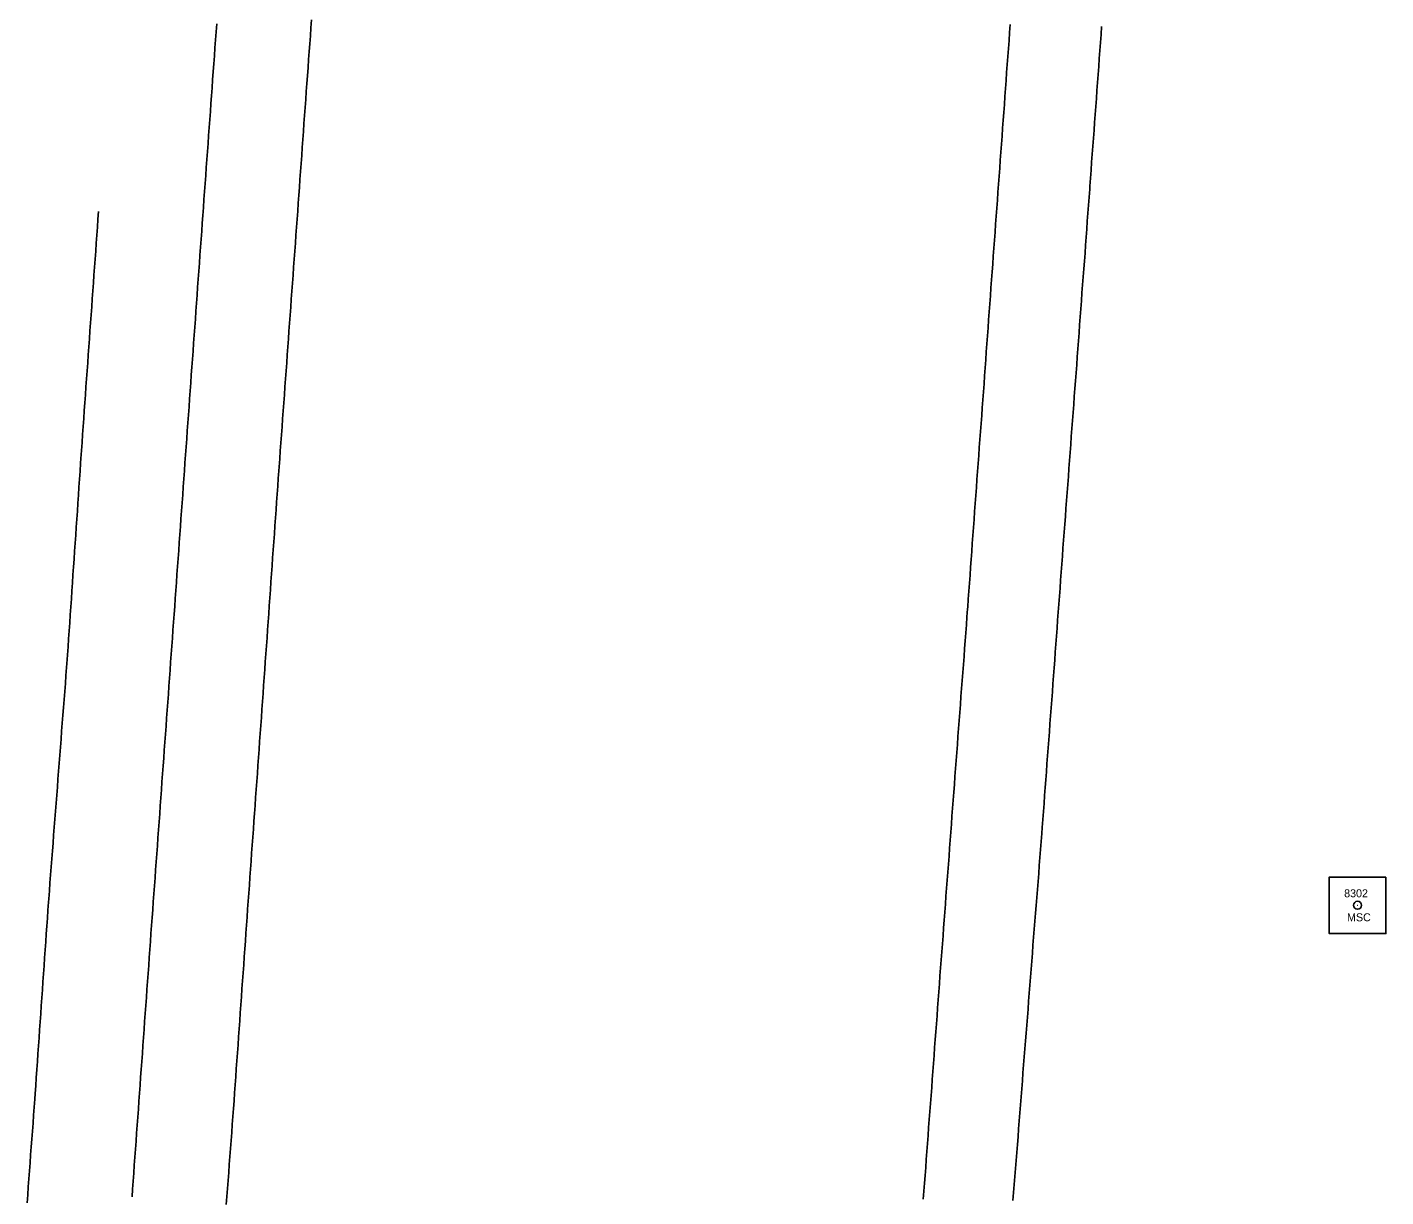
# Model space of a CAD drawing. Extents: x 205929 to 2357175, y -1785700 to 846739.
# Drawn here: x 2023342.3 to 2023512, y 808641.8 to 808787.9 of the extents above; entities that cross this region are included whole.
import ezdxf

# ---------------------------------------------------------------- set-up
doc = ezdxf.new("R2010")
doc.units = 0
for name, color, linetype in [('RD_HC_Survey', 7, 'Continuous'), ('RD_HC_txCode', 7, 'Continuous'), ('RD_Sketch1', 7, 'Continuous'), ('RD_SMD_Locator', 7, 'Continuous')]:
    doc.layers.add(name, color=color, linetype=linetype)

msp = doc.modelspace()

# ---------------------------------------------------------------- linework, layer by layer
at = {"layer": 'RD_HC_Survey'}
msp.add_lwpolyline([(2023512.02, 808681.73), (2023504.95, 808681.73), (2023504.95, 808674.66), (2023512.02, 808674.66)], close=True, dxfattribs=at)
msp.add_circle((2023508.48, 808678.2), 0.5, dxfattribs=at)
at = {"layer": 'RD_Sketch1'}
for points in [[(2023365.93, 808788.35), (2023365.85, 808787.35), (2023365.78, 808786.36), (2023365.71, 808785.36), (2023365.64, 808784.36), (2023365.57, 808783.36), (2023365.49, 808782.37), (2023365.42, 808781.37), (2023365.35, 808780.37), (2023365.28, 808779.37), (2023365.21, 808778.38), (2023365.14, 808777.38), (2023365.06, 808776.38), (2023364.99, 808775.39), (2023364.92, 808774.39), (2023364.85, 808773.39), (2023364.78, 808772.39), (2023364.7, 808771.4), (2023364.63, 808770.4), (2023364.56, 808769.4), (2023364.49, 808768.4), (2023364.42, 808767.41), (2023364.34, 808766.41), (2023364.27, 808765.41), (2023364.2, 808764.41), (2023364.13, 808763.42), (2023364.06, 808762.42), (2023363.98, 808761.42), (2023363.91, 808760.42), (2023363.84, 808759.43), (2023363.77, 808758.43), (2023363.7, 808757.43), (2023363.63, 808756.44), (2023363.55, 808755.44), (2023363.48, 808754.44), (2023363.41, 808753.44), (2023363.34, 808752.45), (2023363.27, 808751.45), (2023363.19, 808750.45), (2023363.12, 808749.45), (2023363.05, 808748.46), (2023362.98, 808747.46), (2023362.91, 808746.46), (2023362.91, 808746.46), (2023362.83, 808745.46), (2023362.76, 808744.47), (2023362.69, 808743.47), (2023362.62, 808742.47), (2023362.55, 808741.47), (2023362.48, 808740.48), (2023362.4, 808739.48), (2023362.33, 808738.48), (2023362.26, 808737.48), (2023362.19, 808736.49), (2023362.12, 808735.49), (2023362.04, 808734.49), (2023361.97, 808733.5), (2023361.9, 808732.5), (2023361.83, 808731.5), (2023361.76, 808730.5), (2023361.68, 808729.51), (2023361.61, 808728.51), (2023361.54, 808727.51), (2023361.47, 808726.51), (2023361.4, 808725.53), (2023361.33, 808724.53), (2023361.25, 808723.53), (2023361.18, 808722.54), (2023361.11, 808721.54), (2023361.04, 808720.54), (2023360.97, 808719.54), (2023360.89, 808718.55), (2023360.82, 808717.55), (2023360.75, 808716.55), (2023360.68, 808715.55), (2023360.61, 808714.56), (2023360.53, 808713.56), (2023360.46, 808712.56), (2023360.39, 808711.56), (2023360.32, 808710.57), (2023360.25, 808709.57), (2023360.17, 808708.57), (2023360.1, 808707.57), (2023360.03, 808706.58), (2023359.96, 808705.58), (2023359.89, 808704.58), (2023359.81, 808703.58), (2023359.74, 808702.59), (2023359.67, 808701.59), (2023359.6, 808700.59), (2023359.53, 808699.6), (2023359.45, 808698.6), (2023359.38, 808697.6), (2023359.31, 808696.6), (2023359.24, 808695.61), (2023359.17, 808694.61), (2023359.09, 808693.61), (2023359.02, 808692.61), (2023358.95, 808691.62), (2023358.88, 808690.62), (2023358.81, 808689.62), (2023358.73, 808688.62), (2023358.66, 808687.63), (2023358.59, 808686.63), (2023358.52, 808685.63), (2023358.45, 808684.63), (2023358.37, 808683.64), (2023358.3, 808682.64), (2023358.3, 808682.64), (2023358.23, 808681.64), (2023358.16, 808680.64), (2023358.09, 808679.65), (2023358.01, 808678.65), (2023357.94, 808677.65), (2023357.87, 808676.66), (2023357.8, 808675.66), (2023357.72, 808674.66), (2023357.65, 808673.66), (2023357.58, 808672.67), (2023357.51, 808671.67), (2023357.44, 808670.67), (2023357.36, 808669.67), (2023357.29, 808668.68), (2023357.22, 808667.68), (2023357.15, 808666.68), (2023357.08, 808665.68), (2023357, 808664.69), (2023356.93, 808663.69), (2023356.86, 808662.69), (2023356.79, 808661.69), (2023356.72, 808660.7), (2023356.64, 808659.7), (2023356.57, 808658.7), (2023356.5, 808657.7), (2023356.43, 808656.71), (2023356.36, 808655.71), (2023356.28, 808654.71), (2023356.21, 808653.72), (2023356.14, 808652.72), (2023356.07, 808651.72), (2023356, 808650.72), (2023355.92, 808649.73), (2023355.85, 808648.73), (2023355.78, 808647.73), (2023355.71, 808646.73), (2023355.64, 808645.74), (2023355.56, 808644.74), (2023355.49, 808643.74), (2023355.42, 808642.74), (2023355.35, 808641.75)], [(2023377.78, 808788.86), (2023377.71, 808787.86), (2023377.64, 808786.86), (2023377.56, 808785.86), (2023377.49, 808784.87), (2023377.42, 808783.87), (2023377.35, 808782.87), (2023377.28, 808781.87), (2023377.2, 808780.88), (2023377.13, 808779.88), (2023377.06, 808778.88), (2023376.99, 808777.89), (2023376.91, 808776.89), (2023376.84, 808775.89), (2023376.77, 808774.89), (2023376.7, 808773.9), (2023376.63, 808772.9), (2023376.55, 808771.9), (2023376.48, 808770.9), (2023376.41, 808769.91), (2023376.34, 808768.91), (2023376.26, 808767.91), (2023376.19, 808766.92), (2023376.12, 808765.92), (2023376.05, 808764.92), (2023375.98, 808763.92), (2023375.9, 808762.93), (2023375.83, 808761.93), (2023375.76, 808760.93), (2023375.69, 808759.93), (2023375.61, 808758.94), (2023375.54, 808757.94), (2023375.47, 808756.94), (2023375.4, 808755.95), (2023375.33, 808754.95), (2023375.25, 808753.95), (2023375.18, 808752.95), (2023375.11, 808751.96), (2023375.04, 808750.96), (2023374.96, 808749.96), (2023374.89, 808748.97), (2023374.82, 808747.97), (2023374.75, 808746.97), (2023374.68, 808745.97), (2023374.6, 808744.98), (2023374.53, 808743.98), (2023374.53, 808743.98), (2023374.46, 808742.98), (2023374.39, 808741.98), (2023374.31, 808740.99), (2023374.24, 808739.99), (2023374.17, 808738.99), (2023374.1, 808738), (2023374.03, 808737), (2023373.95, 808736), (2023373.88, 808735), (2023373.81, 808734.01), (2023373.74, 808733.01), (2023373.67, 808732.01), (2023373.63, 808731.59), (2023373.56, 808730.59), (2023373.49, 808729.59), (2023373.42, 808728.59), (2023373.35, 808727.6), (2023373.28, 808726.6), (2023373.21, 808725.6), (2023373.14, 808724.6), (2023373.07, 808723.61), (2023373, 808722.61), (2023372.92, 808721.61), (2023372.85, 808720.61), (2023372.78, 808719.62), (2023372.71, 808718.62), (2023372.64, 808717.62), (2023372.57, 808716.62), (2023372.5, 808715.63), (2023372.43, 808714.63), (2023372.36, 808713.63), (2023372.29, 808712.63), (2023372.22, 808711.64), (2023372.14, 808710.64), (2023372.07, 808709.64), (2023372, 808708.64), (2023371.93, 808707.65), (2023371.86, 808706.65), (2023371.79, 808705.65), (2023371.72, 808704.66), (2023371.65, 808703.66), (2023371.58, 808702.66), (2023371.51, 808701.66), (2023371.43, 808700.67), (2023371.36, 808699.67), (2023371.29, 808698.67), (2023371.22, 808697.67), (2023371.15, 808696.68), (2023371.08, 808695.68), (2023371.01, 808694.68), (2023370.94, 808693.68), (2023370.87, 808692.69), (2023370.8, 808691.69), (2023370.73, 808690.69), (2023370.65, 808689.69), (2023370.58, 808688.7), (2023370.51, 808687.7), (2023370.44, 808686.7), (2023370.37, 808685.7), (2023370.3, 808684.71), (2023370.23, 808683.71), (2023370.16, 808682.71), (2023370.09, 808681.71), (2023370.02, 808680.72), (2023370.02, 808680.72), (2023369.94, 808679.72), (2023369.87, 808678.72), (2023369.8, 808677.72), (2023369.73, 808676.73), (2023369.66, 808675.73), (2023369.59, 808674.73), (2023369.52, 808673.73), (2023369.45, 808672.74), (2023369.38, 808671.74), (2023369.31, 808670.74), (2023369.24, 808669.74), (2023369.16, 808668.75), (2023369.09, 808667.75), (2023369.02, 808666.75), (2023368.95, 808665.75), (2023368.88, 808664.76), (2023368.81, 808663.76), (2023368.74, 808662.76), (2023368.67, 808661.76), (2023368.6, 808660.77), (2023368.53, 808659.77), (2023368.45, 808658.77), (2023368.38, 808657.77), (2023368.31, 808656.78), (2023368.24, 808655.78), (2023368.17, 808654.78), (2023368.1, 808653.78), (2023368.03, 808652.79), (2023367.96, 808651.8), (2023367.88, 808650.8), (2023367.81, 808649.81), (2023367.73, 808648.81), (2023367.65, 808647.81), (2023367.58, 808646.82), (2023367.5, 808645.82), (2023367.43, 808644.82), (2023367.35, 808643.82), (2023367.27, 808642.83), (2023367.2, 808641.83), (2023367.12, 808640.83)], [(2023465.08, 808788.25), (2023465.01, 808787.26), (2023464.94, 808786.26), (2023464.86, 808785.26), (2023464.79, 808784.26), (2023464.72, 808783.27), (2023464.64, 808782.27), (2023464.57, 808781.27), (2023464.5, 808780.27), (2023464.43, 808779.28), (2023464.35, 808778.28), (2023464.28, 808777.28), (2023464.21, 808776.29), (2023464.14, 808775.29), (2023464.06, 808774.29), (2023463.99, 808773.29), (2023463.92, 808772.3), (2023463.84, 808771.3), (2023463.77, 808770.3), (2023463.7, 808769.3), (2023463.63, 808768.31), (2023463.55, 808767.31), (2023463.48, 808766.31), (2023463.41, 808765.32), (2023463.33, 808764.32), (2023463.26, 808763.32), (2023463.19, 808762.32), (2023463.12, 808761.33), (2023463.04, 808760.33), (2023462.97, 808759.33), (2023462.9, 808758.33), (2023462.83, 808757.34), (2023462.75, 808756.34), (2023462.68, 808755.34), (2023462.61, 808754.35), (2023462.53, 808753.35), (2023462.46, 808752.35), (2023462.39, 808751.35), (2023462.32, 808750.36), (2023462.24, 808749.36), (2023462.17, 808748.36), (2023462.1, 808747.36), (2023462.03, 808746.37), (2023461.95, 808745.37), (2023461.88, 808744.37), (2023461.81, 808743.37), (2023461.73, 808742.38), (2023461.66, 808741.38), (2023461.59, 808740.38), (2023461.52, 808739.39), (2023461.44, 808738.39), (2023461.37, 808737.39), (2023461.3, 808736.39), (2023461.22, 808735.4), (2023461.15, 808734.4), (2023461.08, 808733.4), (2023461.01, 808732.4), (2023460.93, 808731.41), (2023460.86, 808730.41), (2023460.79, 808729.41), (2023460.72, 808728.42), (2023460.64, 808727.42), (2023460.64, 808727.42), (2023460.57, 808726.42), (2023460.5, 808725.42), (2023460.42, 808724.43), (2023460.35, 808723.43), (2023460.28, 808722.43), (2023460.21, 808721.43), (2023460.13, 808720.44), (2023460.06, 808719.44), (2023459.99, 808718.44), (2023459.91, 808717.45), (2023459.84, 808716.45), (2023459.77, 808715.45), (2023459.75, 808715.25), (2023459.68, 808714.26), (2023459.61, 808713.26), (2023459.53, 808712.26), (2023459.46, 808711.26), (2023459.38, 808710.27), (2023459.31, 808709.27), (2023459.23, 808708.27), (2023459.16, 808707.27), (2023459.08, 808706.28), (2023459.01, 808705.28), (2023458.93, 808704.28), (2023458.86, 808703.29), (2023458.78, 808702.29), (2023458.71, 808701.29), (2023458.63, 808700.29), (2023458.56, 808699.3), (2023458.48, 808698.3), (2023458.41, 808697.3), (2023458.33, 808696.31), (2023458.26, 808695.31), (2023458.18, 808694.31), (2023458.11, 808693.31), (2023458.03, 808692.32), (2023457.96, 808691.32), (2023457.88, 808690.32), (2023457.81, 808689.33), (2023457.74, 808688.33), (2023457.66, 808687.33), (2023457.59, 808686.33), (2023457.51, 808685.34), (2023457.44, 808684.34), (2023457.36, 808683.34), (2023457.29, 808682.35), (2023457.21, 808681.35), (2023457.14, 808680.35), (2023457.06, 808679.35), (2023456.99, 808678.36), (2023456.91, 808677.36), (2023456.84, 808676.36), (2023456.76, 808675.37), (2023456.69, 808674.37), (2023456.61, 808673.37), (2023456.54, 808672.37), (2023456.46, 808671.38), (2023456.39, 808670.38), (2023456.31, 808669.38), (2023456.24, 808668.39), (2023456.16, 808667.39), (2023456.09, 808666.39), (2023456.01, 808665.39), (2023455.94, 808664.4), (2023455.94, 808664.4), (2023455.87, 808663.4), (2023455.79, 808662.4), (2023455.72, 808661.41), (2023455.64, 808660.41), (2023455.57, 808659.41), (2023455.49, 808658.41), (2023455.42, 808657.42), (2023455.34, 808656.42), (2023455.27, 808655.42), (2023455.19, 808654.43), (2023455.12, 808653.43), (2023455.04, 808652.43), (2023454.97, 808651.43), (2023454.89, 808650.44), (2023454.82, 808649.44), (2023454.74, 808648.44), (2023454.67, 808647.44), (2023454.59, 808646.45), (2023454.52, 808645.45), (2023454.44, 808644.45), (2023454.37, 808643.46), (2023454.29, 808642.46), (2023454.22, 808641.46)], [(2023476.51, 808788), (2023476.43, 808787), (2023476.36, 808786.01), (2023476.29, 808785.01), (2023476.21, 808784.01), (2023476.14, 808783.02), (2023476.07, 808782.02), (2023476, 808781.02), (2023475.92, 808780.02), (2023475.85, 808779.03), (2023475.78, 808778.03), (2023475.7, 808777.03), (2023475.63, 808776.03), (2023475.56, 808775.04), (2023475.48, 808774.04), (2023475.41, 808773.04), (2023475.34, 808772.04), (2023475.26, 808771.05), (2023475.19, 808770.05), (2023475.12, 808769.05), (2023475.05, 808768.06), (2023475.02, 808767.69), (2023474.94, 808766.69), (2023474.87, 808765.69), (2023474.8, 808764.7), (2023474.72, 808763.7), (2023474.65, 808762.7), (2023474.57, 808761.7), (2023474.5, 808760.71), (2023474.43, 808759.71), (2023474.35, 808758.71), (2023474.28, 808757.72), (2023474.2, 808756.72), (2023474.13, 808755.72), (2023474.05, 808754.72), (2023473.98, 808753.73), (2023473.91, 808752.73), (2023473.83, 808751.73), (2023473.76, 808750.74), (2023473.68, 808749.74), (2023473.61, 808748.74), (2023473.54, 808747.74), (2023473.46, 808746.75), (2023473.39, 808745.75), (2023473.31, 808744.75), (2023473.24, 808743.75), (2023473.16, 808742.76), (2023473.09, 808741.76), (2023473.02, 808740.76), (2023472.94, 808739.77), (2023472.87, 808738.77), (2023472.79, 808737.77), (2023472.72, 808736.77), (2023472.65, 808735.78), (2023472.57, 808734.78), (2023472.5, 808733.78), (2023472.42, 808732.79), (2023472.35, 808731.79), (2023472.27, 808730.79), (2023472.2, 808729.79), (2023472.13, 808728.8), (2023472.05, 808727.8), (2023471.98, 808726.8), (2023471.9, 808725.81), (2023471.9, 808725.81), (2023471.83, 808724.81), (2023471.76, 808723.81), (2023471.68, 808722.81), (2023471.61, 808721.82), (2023471.53, 808720.82), (2023471.46, 808719.82), (2023471.38, 808718.82), (2023471.31, 808717.83), (2023471.24, 808716.83), (2023471.16, 808715.83), (2023471.09, 808714.84), (2023471.01, 808713.84), (2023470.94, 808712.84), (2023470.87, 808711.84), (2023470.79, 808710.85), (2023470.72, 808709.85), (2023470.64, 808708.85), (2023470.57, 808707.86), (2023470.49, 808706.86), (2023470.42, 808705.86), (2023470.35, 808704.86), (2023470.27, 808703.87), (2023470.2, 808702.87), (2023470.12, 808701.87), (2023470.05, 808700.87), (2023469.98, 808699.88), (2023469.9, 808698.88), (2023469.83, 808697.88), (2023469.75, 808696.89), (2023469.68, 808695.89), (2023469.6, 808694.89), (2023469.53, 808693.89), (2023469.46, 808692.9), (2023469.38, 808691.9), (2023469.31, 808690.9), (2023469.23, 808689.91), (2023469.16, 808688.91), (2023469.09, 808687.91), (2023469.03, 808687.17), (2023468.95, 808686.17), (2023468.87, 808685.17), (2023468.79, 808684.17), (2023468.72, 808683.18), (2023468.64, 808682.18), (2023468.56, 808681.18), (2023468.48, 808680.19), (2023468.4, 808679.19), (2023468.33, 808678.19), (2023468.25, 808677.2), (2023468.17, 808676.2), (2023468.09, 808675.2), (2023468.01, 808674.21), (2023467.93, 808673.21), (2023467.86, 808672.21), (2023467.78, 808671.22), (2023467.7, 808670.22), (2023467.62, 808669.22), (2023467.54, 808668.22), (2023467.46, 808667.23), (2023467.39, 808666.23), (2023467.31, 808665.23), (2023467.23, 808664.24), (2023467.15, 808663.24), (2023467.07, 808662.24), (2023467.07, 808662.24), (2023466.99, 808661.25), (2023466.92, 808660.25), (2023466.84, 808659.25), (2023466.76, 808658.26), (2023466.68, 808657.26), (2023466.6, 808656.26), (2023466.52, 808655.26), (2023466.45, 808654.27), (2023466.37, 808653.27), (2023466.29, 808652.27), (2023466.21, 808651.28), (2023466.13, 808650.28), (2023466.06, 808649.28), (2023465.98, 808648.29), (2023465.9, 808647.29), (2023465.82, 808646.29), (2023465.74, 808645.3), (2023465.66, 808644.3), (2023465.59, 808643.3), (2023465.51, 808642.31), (2023465.43, 808641.31)], [(2023342.25, 808641.01), (2023342.32, 808642.01), (2023342.39, 808643.01), (2023342.46, 808644.01), (2023342.54, 808645), (2023342.61, 808646), (2023342.68, 808647), (2023342.76, 808648), (2023342.83, 808648.99), (2023342.9, 808649.99), (2023342.98, 808650.99), (2023343.05, 808651.98), (2023343.12, 808652.98), (2023343.2, 808653.98), (2023343.25, 808654.67), (2023343.32, 808655.66), (2023343.38, 808656.66), (2023343.45, 808657.66), (2023343.52, 808658.66), (2023343.59, 808659.65), (2023343.66, 808660.65), (2023343.73, 808661.65), (2023343.8, 808662.65), (2023343.87, 808663.64), (2023343.94, 808664.64), (2023344.01, 808665.64), (2023344.08, 808666.64), (2023344.08, 808666.64), (2023344.15, 808667.63), (2023344.22, 808668.63), (2023344.29, 808669.63), (2023344.36, 808670.63), (2023344.43, 808671.62), (2023344.5, 808672.62), (2023344.57, 808673.62), (2023344.64, 808674.62), (2023344.71, 808675.61), (2023344.78, 808676.61), (2023344.85, 808677.61), (2023344.92, 808678.61), (2023344.95, 808679), (2023345.02, 808680), (2023345.1, 808681), (2023345.18, 808681.99), (2023345.25, 808682.99), (2023345.33, 808683.99), (2023345.41, 808684.99), (2023345.48, 808685.98), (2023345.56, 808686.98), (2023345.64, 808687.98), (2023345.71, 808688.97), (2023345.79, 808689.97), (2023345.87, 808690.97), (2023345.94, 808691.96), (2023346.02, 808692.96), (2023346.1, 808693.96), (2023346.17, 808694.96), (2023346.25, 808695.95), (2023346.33, 808696.95), (2023346.4, 808697.95), (2023346.48, 808698.94), (2023346.56, 808699.94), (2023346.63, 808700.94), (2023346.71, 808701.94), (2023346.79, 808702.93), (2023346.86, 808703.93), (2023346.94, 808704.93), (2023347.02, 808705.92), (2023347.09, 808706.92), (2023347.17, 808707.92), (2023347.25, 808708.91), (2023347.29, 808709.5), (2023347.36, 808710.5), (2023347.43, 808711.5), (2023347.5, 808712.5), (2023347.56, 808713.49), (2023347.63, 808714.49), (2023347.7, 808715.49), (2023347.77, 808716.49), (2023347.84, 808717.48), (2023347.91, 808718.48), (2023347.97, 808719.48), (2023348.04, 808720.48), (2023348.11, 808721.47), (2023348.18, 808722.47), (2023348.25, 808723.47), (2023348.31, 808724.47), (2023348.38, 808725.46), (2023348.45, 808726.46), (2023348.52, 808727.46), (2023348.59, 808728.46), (2023348.66, 808729.45), (2023348.66, 808729.45), (2023348.72, 808730.45), (2023348.79, 808731.45), (2023348.86, 808732.45), (2023348.93, 808733.45), (2023348.97, 808734.02), (2023349.04, 808735.02), (2023349.11, 808736.02), (2023349.18, 808737.01), (2023349.25, 808738.01), (2023349.32, 808739.01), (2023349.39, 808740.01), (2023349.46, 808741), (2023349.53, 808742), (2023349.6, 808743), (2023349.67, 808744), (2023349.75, 808744.99), (2023349.82, 808745.99), (2023349.89, 808746.99), (2023349.96, 808747.99), (2023350.03, 808748.98), (2023350.1, 808749.98), (2023350.17, 808750.98), (2023350.24, 808751.98), (2023350.31, 808752.97), (2023350.38, 808753.97), (2023350.45, 808754.97), (2023350.52, 808755.97), (2023350.59, 808756.96), (2023350.66, 808757.96), (2023350.73, 808758.96), (2023350.81, 808759.96), (2023350.88, 808760.95), (2023350.95, 808761.95), (2023351.02, 808762.95), (2023351.09, 808763.95), (2023351.16, 808764.89)]]:
    msp.add_lwpolyline(points, dxfattribs=at)
at = {"layer": 'RD_SMD_Locator'}
msp.add_circle((2023508.48, 808678.2), 0.001, dxfattribs=at)

# ---------------------------------------------------------------- texts
at = {"layer": 'RD_HC_txCode'}
for s, p in [('8302', (2023506.81, 808679.2)), ('MSC', (2023507.17, 808676.2))]:
    msp.add_text(s, height=1, dxfattribs=at).set_placement(p)

doc.saveas('drawing.dxf')
